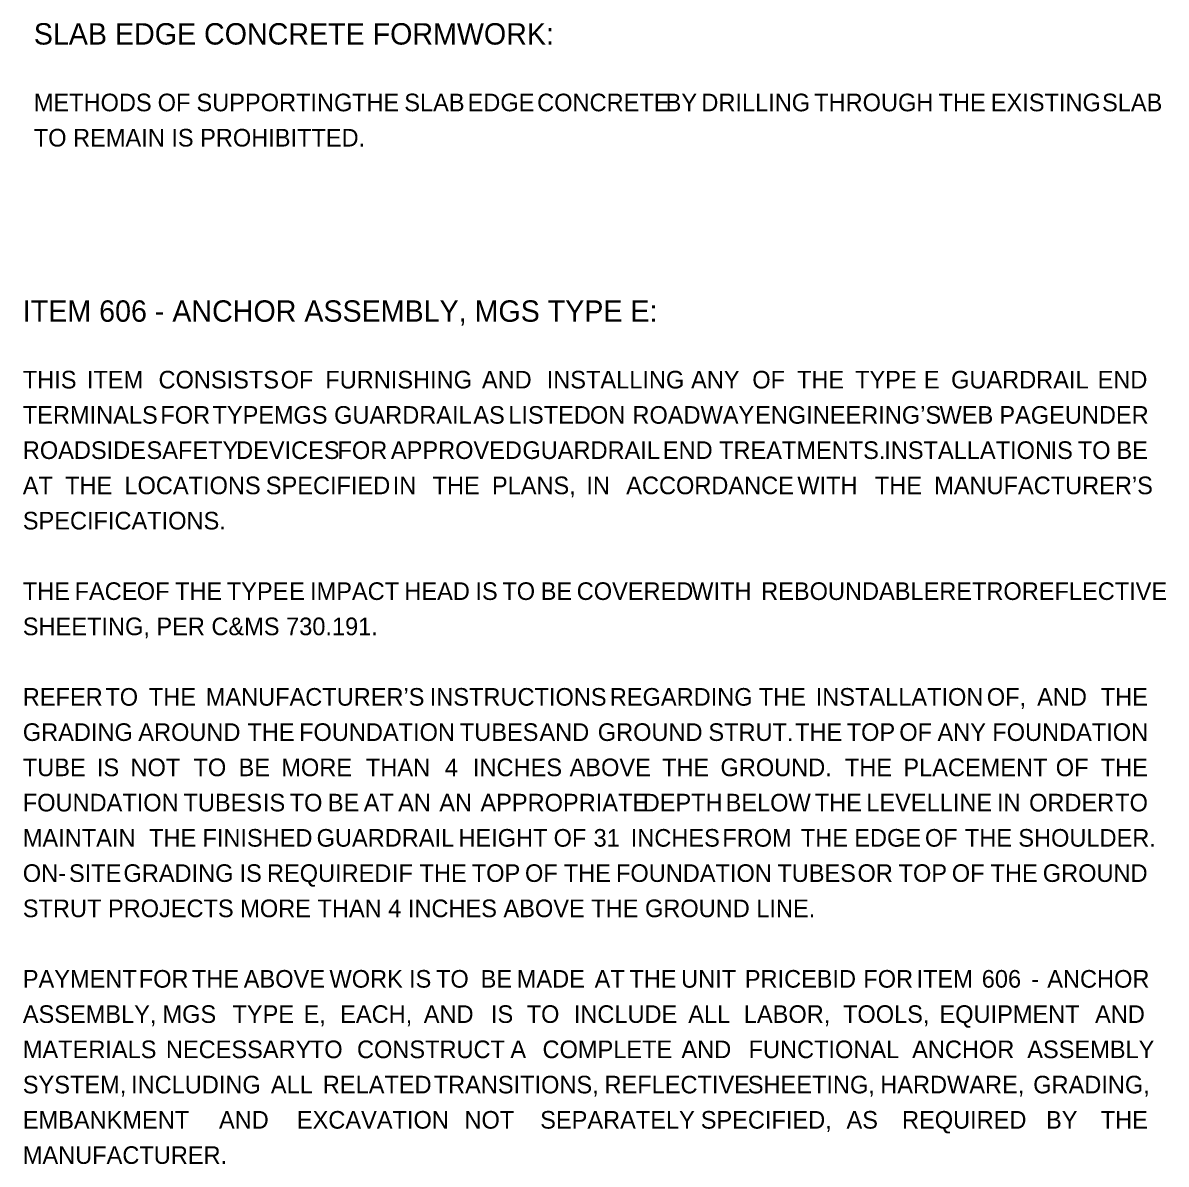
# Model space of a CAD drawing. Extents: x 0 to 44.4, y -4.7 to 22.
# Drawn here: x 35.17 to 44.25, y -4.68 to 4.39 of the extents above; entities that cross this region are included whole.
import ezdxf

# ---------------------------------------------------------------- set-up
doc = ezdxf.new("R2010")
doc.units = 0
doc.layers.add('SH_Text', color=7, linetype='Continuous')

msp = doc.modelspace()

# ---------------------------------------------------------------- texts
at = {"layer": 'SH_Text'}
for s, height, p in [('SLAB EDGE CONCRETE FORMWORK:', 0.17, (35.2581, 4.2187)), ('METHODS ', 0.14, (35.2581, 3.6887)), ('OF ', 0.14, (36.2416, 3.6887)), ('SUPPORTING ', 0.14, (36.5499, 3.6887)), ('THE ', 0.14, (37.785, 3.6887)), ('SLAB ', 0.14, (38.2002, 3.6887)), ('EDGE ', 0.14, (38.7028, 3.6887)), ('CONCRETE ', 0.14, (39.2556, 3.6887)), ('BY ', 0.14, (40.2758, 3.6887)), ('DRILLING ', 0.14, (40.5595, 3.6887)), ('THROUGH ', 0.14, (41.4555, 3.6887)), ('THE ', 0.14, (42.4432, 3.6887)), ('EXISTING ', 0.14, (42.8584, 3.6887)), ('SLAB ', 0.14, (43.7416, 3.6887)), ('TO REMAIN IS PROHIBITTED.', 0.14, (35.2581, 3.4087)), ('ITEM 606 - ANCHOR ASSEMBLY, MGS TYPE E:', 0.17, (35.1708, 2.0167)), ('THIS ', 0.14, (35.1708, 1.4867)), ('ITEM ', 0.14, (35.6801, 1.4867)), ('CONSISTS ', 0.14, (36.2486, 1.4867)), ('OF ', 0.14, (37.2183, 1.4867)), ('FURNISHING ', 0.14, (37.573, 1.4867)), ('AND ', 0.14, (38.8167, 1.4867)), ('INSTALLING ', 0.14, (39.3313, 1.4867)), ('ANY ', 0.14, (40.4777, 1.4867)), ('OF ', 0.14, (40.9641, 1.4867)), ('THE ', 0.14, (41.3188, 1.4867)), ('TYPE ', 0.14, (41.7804, 1.4867)), ('E ', 0.14, (42.3261, 1.4867)), ('GUARDRAIL ', 0.14, (42.5427, 1.4867)), ('END ', 0.14, (43.7063, 1.4867)), ('TERMINALS ', 0.14, (35.1708, 1.2067)), ('FOR ', 0.14, (36.2631, 1.2067)), ('TYPE ', 0.14, (36.6773, 1.2067)), ('MGS ', 0.14, (37.1648, 1.2067)), ('GUARDRAIL ', 0.14, (37.6431, 1.2067)), ('AS ', 0.14, (38.7484, 1.2067)), ('LISTED ', 0.14, (39.0266, 1.2067)), ('ON ', 0.14, (39.6748, 1.2067)), ('ROADWAY ', 0.14, (40.0121, 1.2067)), ('ENGINEERING’S ', 0.14, (40.9866, 1.2067)), ('WEB ', 0.14, (42.4513, 1.2067)), ('PAGE ', 0.14, (42.9261, 1.2067)), ('UNDER ', 0.14, (43.4461, 1.2067)), ('ROADSIDE ', 0.14, (35.1708, 0.9267)), ('SAFETY ', 0.14, (36.1533, 0.9267)), ('DEVICES ', 0.14, (36.8644, 0.9267)), ('FOR ', 0.14, (37.6699, 0.9267)), ('APPROVED ', 0.14, (38.0942, 0.9267)), ('GUARDRAIL ', 0.14, (39.1385, 0.9267)), ('END ', 0.14, (40.2538, 0.9267)), ('TREATMENTS. ', 0.14, (40.7002, 0.9267)), ('INSTALLATION ', 0.14, (42.0122, 0.9267)), ('IS ', 0.14, (43.3326, 0.9267)), ('TO ', 0.14, (43.5488, 0.9267)), ('BE ', 0.14, (43.8559, 0.9267)), ('AT ', 0.14, (35.1708, 0.6467)), ('THE ', 0.14, (35.5066, 0.6467)), ('LOCATIONS ', 0.14, (35.9778, 0.6467)), ('SPECIFIED ', 0.14, (37.1005, 0.6467)), ('IN ', 0.14, (38.1084, 0.6467)), ('THE ', 0.14, (38.4249, 0.6467)), ('PLANS, ', 0.14, (38.8962, 0.6467)), ('IN ', 0.14, (39.6462, 0.6467)), ('ACCORDANCE ', 0.14, (39.9628, 0.6467)), ('WITH ', 0.14, (41.3216, 0.6467)), ('THE ', 0.14, (41.9372, 0.6467)), ('MANUFACTURER’S ', 0.14, (42.4084, 0.6467)), ('SPECIFICATIONS.', 0.14, (35.1708, 0.3667)), ('THE ', 0.14, (35.1708, -0.1933)), ('FACE ', 0.14, (35.5818, -0.1933)), ('OF ', 0.14, (36.0755, -0.1933)), ('THE ', 0.14, (36.3796, -0.1933)), ('TYPE ', 0.14, (36.7906, -0.1933)), ('E ', 0.14, (37.2858, -0.1933)), ('IMPACT ', 0.14, (37.4519, -0.1933)), ('HEAD ', 0.14, (38.2008, -0.1933)), ('IS ', 0.14, (38.7652, -0.1933)), ('TO ', 0.14, (38.9791, -0.1933)), ('BE ', 0.14, (39.2837, -0.1933)), ('COVERED ', 0.14, (39.5698, -0.1933)), ('WITH ', 0.14, (40.4789, -0.1933)), ('REBOUNDABLE ', 0.14, (41.0343, -0.1933)), ('RETROREFLECTIVE ', 0.14, (42.4485, -0.1933)), ('SHEETING, PER C&MS 730.191.', 0.14, (35.1708, -0.4733)), ('REFER ', 0.14, (35.1708, -1.0333)), ('TO ', 0.14, (35.8262, -1.0333)), ('THE ', 0.14, (36.1716, -1.0333)), ('MANUFACTURER’S ', 0.14, (36.6234, -1.0333)), ('INSTRUCTIONS ', 0.14, (38.4025, -1.0333)), ('REGARDING ', 0.14, (39.8325, -1.0333)), ('THE ', 0.14, (41.0157, -1.0333)), ('INSTALLATION ', 0.14, (41.4675, -1.0333)), ('OF, ', 0.14, (42.8263, -1.0333)), ('AND ', 0.14, (43.2262, -1.0333)), ('THE ', 0.14, (43.731, -1.0333)), ('GRADING ', 0.14, (35.1708, -1.3133)), ('AROUND ', 0.14, (36.0878, -1.3133)), ('THE ', 0.14, (36.9547, -1.3133)), ('FOUNDATION ', 0.14, (37.3649, -1.3133)), ('TUBES ', 0.14, (38.6415, -1.3133)), ('AND ', 0.14, (39.2736, -1.3133)), ('GROUND ', 0.14, (39.7368, -1.3133)), ('STRUT. ', 0.14, (40.6153, -1.3133)), ('THE ', 0.14, (41.3034, -1.3133)), ('TOP ', 0.14, (41.7136, -1.3133)), ('OF ', 0.14, (42.1314, -1.3133)), ('ANY ', 0.14, (42.4348, -1.3133)), ('FOUNDATION ', 0.14, (42.8698, -1.3133)), ('IS ', 0.14, (35.7593, -1.5933)), ('NOT ', 0.14, (36.0264, -1.5933)), ('TO ', 0.14, (36.5264, -1.5933)), ('MORE ', 0.14, (37.2237, -1.5933)), ('INCHES ', 0.14, (38.7457, -1.5933)), ('ABOVE ', 0.14, (39.5132, -1.5933)), ('GROUND. ', 0.14, (40.7112, -1.5933)), ('PLACEMENT ', 0.14, (42.1637, -1.5933)), ('OF ', 0.14, (43.3736, -1.5933)), ('TUBE ', 0.14, (35.1708, -1.5933)), ('BE ', 0.14, (36.8843, -1.5933)), ('THAN ', 0.14, (37.8958, -1.5933)), ('4 ', 0.14, (38.5223, -1.5933)), ('THE ', 0.14, (40.247, -1.5933)), ('THE ', 0.14, (41.6995, -1.5933)), ('THE ', 0.14, (43.731, -1.5933)), ('FOUNDATION ', 0.14, (35.1708, -1.8733)), ('TUBES ', 0.14, (36.4467, -1.8733)), ('IS ', 0.14, (37.078, -1.8733)), ('TO ', 0.14, (37.2902, -1.8733)), ('BE ', 0.14, (37.5932, -1.8733)), ('AT ', 0.14, (37.8778, -1.8733)), ('AN ', 0.14, (38.1516, -1.8733)), ('AN ', 0.14, (38.4784, -1.8733)), ('APPROPRIATE ', 0.14, (38.8051, -1.8733)), ('DEPTH ', 0.14, (40.0937, -1.8733)), ('BELOW ', 0.14, (40.7519, -1.8733)), ('THE ', 0.14, (41.4602, -1.8733)), ('LEVEL ', 0.14, (41.8696, -1.8733)), ('LINE ', 0.14, (42.4523, -1.8733)), ('IN ', 0.14, (42.9073, -1.8733)), ('ORDER ', 0.14, (43.162, -1.8733)), ('TO ', 0.14, (43.846, -1.8733)), ('MAINTAIN ', 0.14, (35.1708, -2.1533)), ('THE ', 0.14, (36.1732, -2.1533)), ('FINISHED ', 0.14, (36.5973, -2.1533)), ('GUARDRAIL ', 0.14, (37.504, -2.1533)), ('HEIGHT ', 0.14, (38.6301, -2.1533)), ('OF ', 0.14, (39.3864, -2.1533)), ('31 ', 0.14, (39.7036, -2.1533)), ('INCHES ', 0.14, (39.9986, -2.1533)), ('FROM ', 0.14, (40.7259, -2.1533)), ('THE ', 0.14, (41.3495, -2.1533)), ('EDGE ', 0.14, (41.7736, -2.1533)), ('OF ', 0.14, (42.3353, -2.1533)), ('THE ', 0.14, (42.6525, -2.1533)), ('SHOULDER. ', 0.14, (43.0766, -2.1533)), ('ON-', 0.14, (35.1708, -2.4333)), ('SITE ', 0.14, (35.5374, -2.4333)), ('GRADING ', 0.14, (35.9702, -2.4333)), ('IS ', 0.14, (36.8918, -2.4333)), ('REQUIRED ', 0.14, (37.1095, -2.4333)), ('IF ', 0.14, (38.1023, -2.4333)), ('THE ', 0.14, (38.3215, -2.4333)), ('TOP ', 0.14, (38.7363, -2.4333)), ('OF ', 0.14, (39.1588, -2.4333)), ('THE ', 0.14, (39.4667, -2.4333)), ('FOUNDATION ', 0.14, (39.8815, -2.4333)), ('TUBES ', 0.14, (41.1628, -2.4333)), ('OR ', 0.14, (41.7995, -2.4333)), ('TOP ', 0.14, (42.1258, -2.4333)), ('OF ', 0.14, (42.5483, -2.4333)), ('THE ', 0.14, (42.8562, -2.4333)), ('GROUND ', 0.14, (43.271, -2.4333)), ('STRUT PROJECTS MORE THAN 4 INCHES ABOVE THE GROUND LINE.', 0.14, (35.1708, -2.7133)), ('PAYMENT ', 0.14, (35.1708, -3.2733)), ('FOR ', 0.14, (36.0918, -3.2733)), ('THE ', 0.14, (36.5141, -3.2733)), ('ABOVE ', 0.14, (36.9254, -3.2733)), ('WORK ', 0.14, (37.6062, -3.2733)), ('IS ', 0.14, (38.238, -3.2733)), ('TO  ', 0.14, (38.4521, -3.2733)), ('BE ', 0.14, (38.8069, -3.2733)), ('MADE ', 0.14, (39.0934, -3.2733)), ('AT ', 0.14, (39.7117, -3.2733)), ('THE ', 0.14, (39.9875, -3.2733)), ('UNIT ', 0.14, (40.3988, -3.2733)), ('PRICE ', 0.14, (40.9046, -3.2733)), ('BID ', 0.14, (41.4756, -3.2733)), ('FOR ', 0.14, (41.8456, -3.2733)), ('ITEM ', 0.14, (42.2679, -3.2733)), ('606 ', 0.14, (42.7861, -3.2733)), ('ANCHOR ', 0.14, (43.3064, -3.2733)), ('- ', 0.14, (43.1801, -3.2733)), ('ASSEMBLY, ', 0.14, (35.1708, -3.5533)), ('MGS ', 0.14, (36.28, -3.5533)), ('TYPE ', 0.14, (36.8357, -3.5533)), ('E, ', 0.14, (37.4005, -3.5533)), ('EACH, ', 0.14, (37.6913, -3.5533)), ('AND ', 0.14, (38.355, -3.5533)), ('IS ', 0.14, (38.8886, -3.5533)), ('TO ', 0.14, (39.1721, -3.5533)), ('INCLUDE ', 0.14, (39.5464, -3.5533)), ('ALL ', 0.14, (40.4556, -3.5533)), ('LABOR, ', 0.14, (40.8967, -3.5533)), ('TOOLS, ', 0.14, (41.6843, -3.5533)), ('EQUIPMENT ', 0.14, (42.4504, -3.5533)), ('AND ', 0.14, (43.6863, -3.5533)), ('MATERIALS ', 0.14, (35.1708, -3.8333)), ('NECESSARY ', 0.14, (36.3072, -3.8333)), ('TO ', 0.14, (37.4508, -3.8333)), ('CONSTRUCT ', 0.14, (37.8246, -3.8333)), ('A ', 0.14, (39.0429, -3.8333)), ('COMPLETE ', 0.14, (39.2981, -3.8333)), ('AND ', 0.14, (40.4013, -3.8333)), ('FUNCTIONAL ', 0.14, (40.9344, -3.8333)), ('ANCHOR ', 0.14, (42.2334, -3.8333)), ('ASSEMBLY ', 0.14, (43.1476, -3.8333)), ('SYSTEM, ', 0.14, (35.1708, -4.1133)), ('INCLUDING ', 0.14, (36.0306, -4.1133)), ('ALL ', 0.14, (37.1408, -4.1133)), ('RELATED ', 0.14, (37.5535, -4.1133)), ('TRANSITIONS, ', 0.14, (38.4337, -4.1133)), ('REFLECTIVE ', 0.14, (39.7905, -4.1133)), ('SHEETING, ', 0.14, (40.9282, -4.1133)), ('HARDWARE, ', 0.14, (41.9801, -4.1133)), ('GRADING, ', 0.14, (43.1949, -4.1133)), ('EMBANKMENT ', 0.14, (35.1708, -4.3933)), ('AND ', 0.14, (36.7286, -4.3933)), ('EXCAVATION ', 0.14, (37.3474, -4.3933)), ('NOT ', 0.14, (38.6781, -4.3933)), ('SEPARATELY ', 0.14, (39.2796, -4.3933)), ('SPECIFIED, ', 0.14, (40.5547, -4.3933)), ('AS ', 0.14, (41.7122, -4.3933)), ('REQUIRED ', 0.14, (42.1529, -4.3933)), ('BY ', 0.14, (43.2967, -4.3933)), ('THE ', 0.14, (43.731, -4.3933)), ('MANUFACTURER.', 0.14, (35.1708, -4.6733))]:
    msp.add_text(s, height=height, dxfattribs=at).set_placement(p)

doc.saveas('drawing.dxf')
